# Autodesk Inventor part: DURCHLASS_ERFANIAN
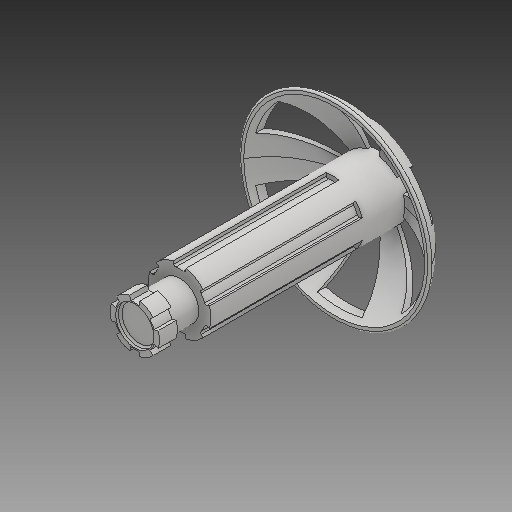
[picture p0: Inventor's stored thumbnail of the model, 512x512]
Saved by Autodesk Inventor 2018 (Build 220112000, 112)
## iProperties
Created: 2019-01
Part Number: DURCHLASS_ERFANIAN
Material: Polypropylene (PP)
Document SubType Name: Modeling
Designer: zand
Density: 0.902188 g/cm^3
Appearance: Vorgabe
Mass: 0.859492 g
Surface Area: 13.4936 cm^2
Volume: 0.952674 cm^3
Author: zand
Revision Number: 11LAST_VERSION
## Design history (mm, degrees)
feature "Basis1"
node "Volumenkörper1"
